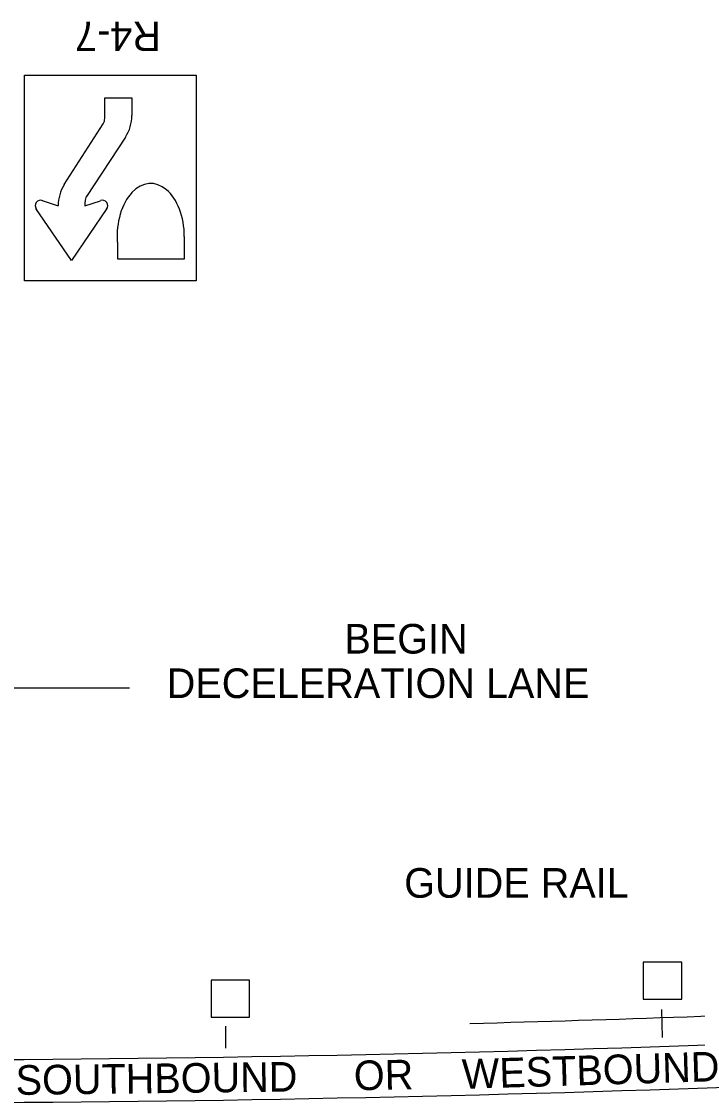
# Model space of a CAD drawing. Extents: x 640253 to 641999, y 298458 to 299646.
# Drawn here: x 641635.9 to 641704.3, y 299419 to 299527.7 of the extents above; entities that cross this region are included whole.
import ezdxf

# ---------------------------------------------------------------- set-up
doc = ezdxf.new("R2010")
doc.units = 0
doc.layers.add('2', color=7, linetype='Continuous')

msp = doc.modelspace()

# ---------------------------------------------------------------- linework, layer by layer
at = {"layer": '2'}
for p, q in [((641644.31, 299517.9), (641644.31, 299520.01)), ((641644.31, 299520.01), (641647.05, 299520.01)), ((641647.05, 299520.01), (641647.05, 299518.21)), ((641640.19, 299511.21), (641644.13, 299517.37)), ((641646.41, 299516.02), (641642.45, 299510.01)), ((641640.92, 299503.54), (641637.33, 299508.78)), ((641637.95, 299509.6), (641639.57, 299509.08)), ((641644.51, 299508.78), (641640.92, 299503.54)), ((641642.29, 299509.08), (641643.86, 299509.58)), ((641642.29, 299509.48), (641642.29, 299509.08)), ((641644.48, 299508.73), (641644.51, 299508.78)), ((641645.59, 299505.4), (641645.59, 299503.71)), ((641652.36, 299503.71), (641652.36, 299505.95)), ((641645.59, 299503.71), (641652.36, 299503.71)), ((641631.93, 299460.29), (641646.8, 299460.29)), ((641700.78, 299424.9), (641700.7, 299427.73)), ((641656.54, 299423.82), (641656.54, 299426.03))]:
    msp.add_line(p, q, dxfattribs=at)
for points in [[(641636.18, 299501.46), (641636.18, 299522.28), (641653.54, 299522.28), (641653.54, 299501.46)], [(641698.83, 299428.77), (641702.73, 299428.77), (641702.73, 299432.52), (641698.83, 299432.52)], [(641655.07, 299426.96), (641658.96, 299426.96), (641658.96, 299430.7), (641655.07, 299430.7)]]:
    msp.add_lwpolyline(points, close=True, dxfattribs=at)
for centre, radius, start, end in [((641643.32, 299517.9), 0.976, 327.4332, 0), ((641643.13, 299518.17), 3.91, 326.6949, 0.6095), ((641643.49, 299509.09), 3.91, 147.3665, 180), ((641643.28, 299509.5), 0.976, 146.6894, 180), ((641637.81, 299509.08), 0.547, 67.919, 221.2726), ((641644.06, 299509.08), 0.547, 320.3028, 110.6097), ((641618.76, 301866.5), 2443.88, 270.0023, 274.32557), ((641617.17, 301869.36), 2443.88, 271.50321, 272.53479), ((641618.76, 301866.5), 2448.22, 270.0023, 274.31789)]:
    msp.add_arc(centre, radius, start, end, dxfattribs=at)
msp.add_ellipse((641648.95, 299505.96), major_axis=(0, 5.37), ratio=0.633721, start_param=4.712389, end_param=7.959212, dxfattribs=at)

# ---------------------------------------------------------------- texts
for s, rotation, p in [('R4-7', 180, (641649.99, 299527.72)), ('WESTBOUND', 1.7407, (641680.51, 299419.69)), ('SOUTHBOUND', 0.7104, (641635.29, 299419.08)), ('OR', 1.2267, (641669.55, 299419.54))]:
    msp.add_text(s, height=3, rotation=rotation, dxfattribs=at).set_placement(p)
for s, p in [('BEGIN', (641668.56, 299463.75)), ('DECELERATION LANE', (641650.57, 299459.25)), ('GUIDE RAIL', (641674.62, 299439.04))]:
    msp.add_text(s, height=3, dxfattribs=at).set_placement(p)

doc.saveas('drawing.dxf')
